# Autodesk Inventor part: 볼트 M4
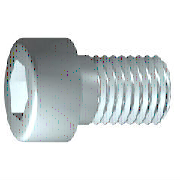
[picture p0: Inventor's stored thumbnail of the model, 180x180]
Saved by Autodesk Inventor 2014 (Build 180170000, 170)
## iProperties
IsCustomPart: 0
Created: 2014-10
Part Number: 볼트 M4
Material: 강철, 연강
Description: 6각머리 태핑 나사
Document SubType Name: Modeling
Standard: KS B 1003
Designer: KYOUNG IL JANG
Standards Organization: KS
Language: ko-KR
Size Designation: M 4 x 10
Categories: <MemberInstance><Categories><Category DisplayName="조임쇠" InternalName="e4da775c-781d-43d5-af7c-5136215cf5a6" Mnemonic="FSTN"><Category DisplayName="볼트" InternalN
Density: 7.86 g/cm^3
Mass: 2.0371 g
Surface Area: 3.0572 cm^2
Volume: 0.259174 cm^3
Appearance: 강철 - 광택
Author: SeoGD™ [www.esajin.kr]
Revision Number: 1
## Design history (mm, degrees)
sketch "스케치1"
  geometry: L1 (-1, 0)-(10, 0); L2 (10, 0)-(10, 2); L3 (10, 2)-(1.75, 2); L4 (1.75, 2)-(1.32, 2); L5 (1.32, 2)-(0, 2); L6 (0, 2)-(0, 3.5); L7 (0, 3.5)-(-4, 3.5); L8 (-4, 3.5)-(-4, 1.732); L9 (-4, 1.732)-(-2, 1.732); L10 (-2, 1.732)-(-1, 0); L11 (-6.8, 0)-(12.8, 0) reference; L12 (0, -0.7)-(0, 4.2) reference; L13 (1.75, 2)-(0, 2)
  constraints: 22 end point, 6 parallel, 2 collinear, 2 perpendicular, 1 horizontal, 1 point on line
  dimensions: "d1" = 8.25 distance from line of L3.end L2 (= GEL); "d2" = 0.42952 distance of L4.end L3.end (computed from GAL); "d3" = 4 distance between parallel lines of L8 L6 (= KOH); "d4" = 2 distance of L8.end L9.end (= INTI); "d5" = 60 deg angle of L10 L1; "d6" = 4 diameter of L3 L1 (= GD); "d7" = 4 diameter of L5 L1 (= BDM); "d8" = 3.4641 diameter of L9 L1 (= 1.1547 x SW); "d9" = 7 diameter of L7 L1 (= KOD); "d26" = 10 distance between parallel lines of L12 L2 (= NLG)
revolve "본체" sketch "스케치1" stored, may be unused: angle "d10" = 90 deg
sketch "스케치2"
  geometry: L1 (0, -4.9)-(0, 4.9) reference; L2 (-4.9, 0)-(4.9, 0) reference; L3 (1.732, 0)-(0.866, -1.5); L4 (0.866, -1.5)-(-0.866, -1.5); L5 (-0.866, -1.5)-(-1.732, 0); L6 (-1.732, 0)-(-0.866, 1.5); L7 (-0.866, 1.5)-(0.866, 1.5); L8 (0.866, 1.5)-(1.732, 0); 2 further points
  constraints: 12 end point, 1 coincident, 1 horizontal alignment, 1 point on line, 12 other
extrude "슬롯" join sketch "스케치2" stored distance "d11" = 10; taper "d12" = 0 deg
workplane "Work Plane1"
fillet "Fillet2" dims "d30" = 0.1 (= R)
body "Solid1"
fillet "모깎기1" dims "d17" = 0.4 (= RR)
feature "스레드" dims "d13" = 8.25 (= GEL), "d14" = 0
chamfer "모따기1" distance "d15" = 0.42941 (= -0.5 x SPD + 0.5 x GD); stored, may be unused: second distance "d16" = 0.42941 (= GUL), angle "d27" = 45 deg
other parameters: "GD" = 4 (= NND) [user parameter; used in 2 equation terms], "NLG" = 10 [user parameter; used in 1 equation term], "GEL" = 8.25 [user parameter; used in 2 equation terms], "KOD" = 7 [user parameter; used in 1 equation term], "KOH" = 4 [user parameter; used in 1 equation term], "INTI" = 2 [user parameter; used in 1 equation term], "GAL" = 0.42941 (= 0.61345 x PTC) [user parameter; used in 1 equation term], "GUL" = 0.42941 (= 0.61345 x PTC) [user parameter; used in 1 equation term], "BDM" = 4 (= NND) [user parameter; used in 1 equation term], "SW" = 3 [user parameter; used in 2 equation terms], "RR" = 0.4 [user parameter; used in 1 equation term], "SPD" = 3.14117 (= NND - 1.2269 x PTC) [user parameter; used in 1 equation term], "d19" = 0, "d28" = 0, "d29" = 0, "R" = 0.1 [user parameter; used in 1 equation term], "PHH" = 0.2 [user parameter], "GD1" = 3.14117 (= THREADDIA - 1.2269 x PTC) [user parameter], "THREADDIA" = 4 [user parameter; used in 1 equation term], "FAWI" = 45 deg [user parameter], "TPU" = 14.28571 (computed from PTC) [user parameter], "PTC" = 0.7 [user parameter; used in 5 equation terms], "NND" = 4 [user parameter; used in 3 equation terms], "TOA" = 30 deg [user parameter], "E0" = 3.465 (= 1.155 x SW) [user parameter]
